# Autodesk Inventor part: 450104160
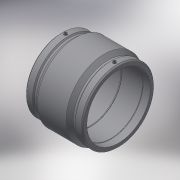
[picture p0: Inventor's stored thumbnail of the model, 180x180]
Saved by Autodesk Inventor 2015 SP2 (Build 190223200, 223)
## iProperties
Created: 2017-06
Part Number: 450104160
Material: Generic
Description: PLASSON COUPLER 160 PN25
Document SubType Name: Modeling
Designer: KIM
Mass: 8622.19 g
Surface Area: 6772.47 cm^2
Volume: 8622.19 cm^3
Density: 1 g/cm^3
Appearance: Default
Author: KIM
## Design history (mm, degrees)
derived "450104.ipt"
feature "Solid1::450104.ipt"
tag "TaggingFeature1"
body "Solid1"
other parameters: "d0" = 198, "d2" = 198, "d3" = 97, "d4" = 49.5, "d5" = 178.2, "d6" = 128, "d8" = 168 deg, "d10" = 38.8, "d11" = 12.93333, "d13" = 198, "d14" = 17.6296, "d15" = 97, "d16" = 97, "d17" = 158.4, "d19" = 3.52592, "d20" = 168 deg, "d22" = 186.12, "d23" = 198, "d24" = 180.5364, "d25" = 135 deg, "d26" = 99, "d27" = 135 deg, "d29" = 105, "d30" = 15, "d31" = 69.3, "d34" = 5 deg, "d35" = 15, "d39" = 5 deg, "d41" = 4, "d42" = 14, "d43" = 0, "d45" = 4, "d46" = 14, "d47" = 0, "d48" = 3, "d49" = 0, "d50" = 3, "d51" = 0, "d52" = 28.13, "d53" = 7.0325, "L_" = 198, "L_1" = 97, "D_" = 198, "A_" = 105, "d_2" = 12
